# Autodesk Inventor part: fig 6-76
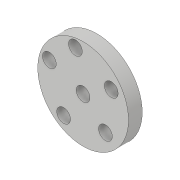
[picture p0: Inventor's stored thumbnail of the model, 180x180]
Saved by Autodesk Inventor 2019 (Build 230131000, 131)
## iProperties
Created: 2018-03
Part Number: fig 6-76
Material: Generic
Document SubType Name: Modeling
Designer: CADCIM 00
Density: 1 g/cm^3
Appearance: Default
Author: CADCIM 00
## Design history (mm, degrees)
sketch "Sketch1"
  geometry: C1 r 16.506 at (0, 0); 1 further point
  constraints: 1 centre point, 1 coincident
extrude "Extrusion1" new body sketch "Sketch1" distance "d0" = 5; taper "d1" = 0 deg
sketch "Sketch3"
  geometry: 2 further points
  constraints: 1 coincident
hole "Hole1" sketch "Sketch3" at (0, 0) diameter "d2" = 5; stored, may be unused: countersink angle "d6" = 90 deg, drill point angle "d8" = 118 deg; dims "d3" = 6, "d4" = 4, "d5" = 2, "d7" = 8
sketch "Sketch2"
  geometry: 6 further points
feature "Sketch Driven Pattern1" sketch "Sketch2"
body "Solid1"
